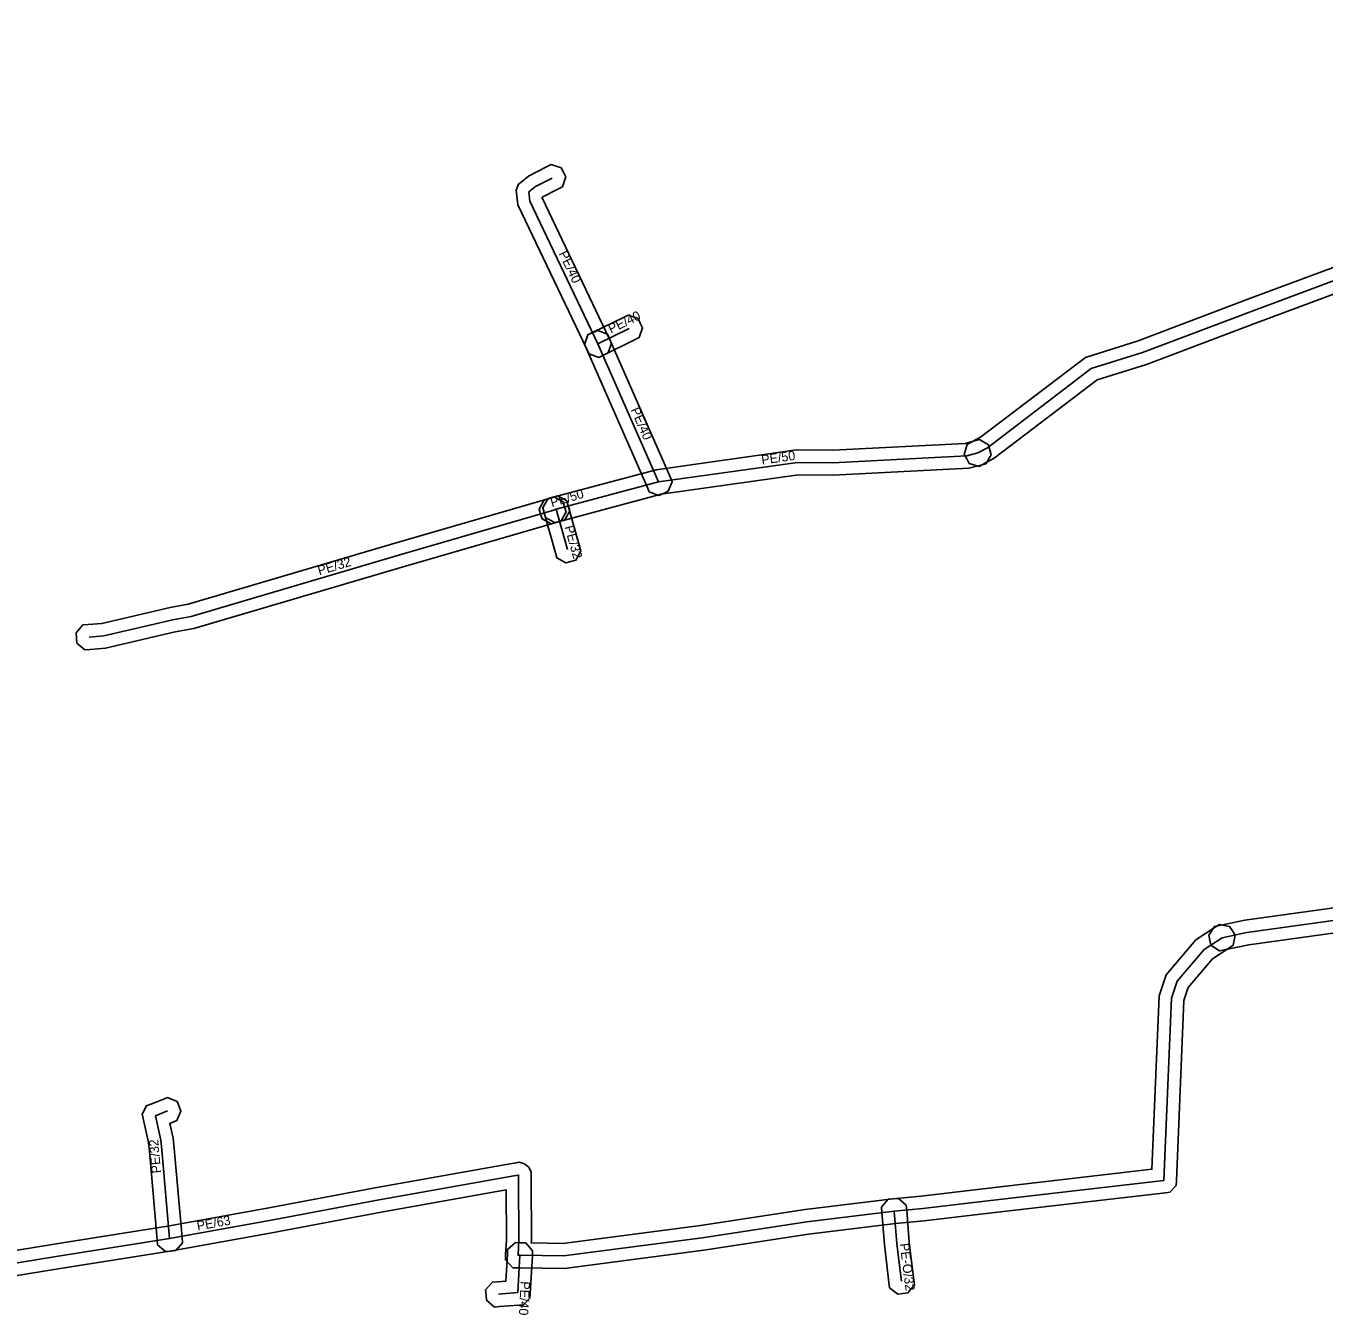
# Model space of a CAD drawing. Extents: x -682697 to -681888, y -1059966 to -1059631.
# Drawn here: x -682102.6 to -681998.6, y -1059783.8 to -1059680.6 of the extents above; entities that cross this region are included whole.
import ezdxf

# ---------------------------------------------------------------- set-up
doc = ezdxf.new("R2010")
doc.units = 0
for name, color, linetype in [('1', 7, 'Continuous'), ('24', 7, 'Continuous'), ('30', 7, 'Continuous')]:
    doc.layers.add(name, color=color, linetype=linetype)

msp = doc.modelspace()

# ---------------------------------------------------------------- linework, layer by layer
at = {"layer": '1'}
for points in [[(-682057.52, -1059706.82), (-682057.7, -1059706.45), (-682063.23, -1059694.88), (-682063.32, -1059693.96), (-682063.35, -1059693.7), (-682063.16, -1059693.23), (-682062.96, -1059693.07), (-682062.36, -1059692.59), (-682060.92, -1059691.85), (-682060.55, -1059691.66), (-682059.76, -1059691.92), (-682059.57, -1059692.28), (-682059.38, -1059692.65), (-682059.64, -1059693.44), (-682060.01, -1059693.63), (-682061.26, -1059694.27), (-682061.28, -1059694.29), (-682061.27, -1059694.32), (-682055.9, -1059705.59), (-682055.72, -1059705.96), (-682055.99, -1059706.74), (-682056.37, -1059706.92), (-682056.74, -1059707.1)], [(-682057.61, -1059705.3), (-682057.24, -1059705.12), (-682054.75, -1059703.9), (-682054.38, -1059703.72), (-682053.59, -1059703.99), (-682053.41, -1059704.36), (-682053.23, -1059704.73), (-682053.5, -1059705.52), (-682053.87, -1059705.7), (-682056.36, -1059706.92), (-682056.73, -1059707.1), (-682057.52, -1059706.83), (-682057.7, -1059706.46), (-682057.88, -1059706.09)], [(-682052.7, -1059717.86), (-682052.87, -1059717.48), (-682057.72, -1059706.42), (-682057.88, -1059706.04), (-682057.58, -1059705.27), (-682057.2, -1059705.1), (-682056.82, -1059704.94), (-682056.05, -1059705.24), (-682055.88, -1059705.62), (-682051.03, -1059716.68), (-682050.87, -1059717.06), (-682051.17, -1059717.83), (-682051.55, -1059718), (-682051.93, -1059718.16)], [(-682025.73, -1059715.63), (-682026.13, -1059715.73), (-682027.09, -1059715.97), (-682037.96, -1059716.54), (-682040.75, -1059716.52), (-682051.75, -1059718.06), (-682059.88, -1059720.24), (-682060.28, -1059720.34), (-682061, -1059719.93), (-682061.11, -1059719.53), (-682061.21, -1059719.13), (-682060.8, -1059718.41), (-682060.4, -1059718.3), (-682052.15, -1059716.1), (-682040.89, -1059714.52), (-682038, -1059714.54), (-682027.39, -1059713.99), (-682026.63, -1059713.79), (-682026.23, -1059713.69), (-682025.51, -1059714.11), (-682025.41, -1059714.51), (-682025.31, -1059714.91)], [(-682059.76, -1059720.2), (-682060.16, -1059720.32), (-682072.4, -1059723.88), (-682089.17, -1059728.82), (-682090.66, -1059729.09), (-682096.24, -1059730.4), (-682097.49, -1059730.5), (-682097.91, -1059730.53), (-682098.54, -1059729.99), (-682098.57, -1059729.58), (-682098.6, -1059729.16), (-682098.06, -1059728.53), (-682097.65, -1059728.5), (-682096.54, -1059728.42), (-682091.06, -1059727.13), (-682089.63, -1059726.88), (-682072.96, -1059721.96), (-682060.72, -1059718.4), (-682060.32, -1059718.28), (-682059.59, -1059718.68), (-682059.48, -1059719.08), (-682059.36, -1059719.48)], [(-682059.46, -1059720.11), (-682059.85, -1059720.23), (-682060.15, -1059720.32), (-682060.55, -1059720.44), (-682061.28, -1059720.04), (-682061.4, -1059719.64), (-682061.52, -1059719.25), (-682061.12, -1059718.52), (-682060.72, -1059718.4), (-682060.43, -1059718.31), (-682060.03, -1059718.19), (-682059.3, -1059718.59), (-682059.18, -1059718.99), (-682059.06, -1059719.38)], [(-682059.29, -1059718.6), (-682059.18, -1059719), (-682058.28, -1059722.22), (-682058.17, -1059722.62), (-682058.57, -1059723.34), (-682058.97, -1059723.45), (-682059.37, -1059723.56), (-682060.09, -1059723.16), (-682060.2, -1059722.76), (-682061.1, -1059719.54), (-682061.21, -1059719.14), (-682060.81, -1059718.42), (-682060.41, -1059718.31), (-682060.01, -1059718.2)], [(-682092.08, -1059778.18), (-682092.12, -1059777.77), (-682092.73, -1059770.67), (-682092.82, -1059769.98), (-682093.24, -1059768.06), (-682093.32, -1059767.71), (-682092.97, -1059767.06), (-682092.63, -1059766.92), (-682091.66, -1059766.53), (-682091.28, -1059766.38), (-682090.52, -1059766.7), (-682090.36, -1059767.09), (-682090.21, -1059767.47), (-682090.53, -1059768.23), (-682090.92, -1059768.39), (-682091.1, -1059768.46), (-682090.84, -1059769.64), (-682090.74, -1059770.47), (-682090.12, -1059777.59), (-682090.09, -1059778.01), (-682090.62, -1059778.64), (-682091.03, -1059778.68), (-682091.45, -1059778.71)], [(-682032.11, -1059775), (-682032.07, -1059775.41), (-682031.86, -1059777.97), (-682031.7, -1059779.3), (-682031.5, -1059780.97), (-682031.45, -1059781.38), (-682031.97, -1059782.03), (-682032.38, -1059782.08), (-682032.79, -1059782.13), (-682033.44, -1059781.61), (-682033.49, -1059781.2), (-682033.68, -1059779.54), (-682033.85, -1059778.17), (-682034.07, -1059775.57), (-682034.1, -1059775.16), (-682033.56, -1059774.53), (-682033.15, -1059774.49), (-682032.74, -1059774.46)], [(-682062.04, -1059778.65), (-682062.06, -1059779.07), (-682062.23, -1059782.07), (-682062.25, -1059782.44), (-682062.78, -1059782.98), (-682063.15, -1059783.01), (-682064.69, -1059783.13), (-682065.1, -1059783.16), (-682065.73, -1059782.62), (-682065.77, -1059782.21), (-682065.8, -1059781.79), (-682065.26, -1059781.17), (-682064.85, -1059781.13), (-682064.18, -1059781.08), (-682064.06, -1059778.95), (-682064.04, -1059778.54), (-682063.42, -1059777.99), (-682063, -1059778.01), (-682062.59, -1059778.03)]]:
    msp.add_lwpolyline(points, close=True, dxfattribs=at)
for points in [[(-681993.93, -1059700.56), (-682004.05, -1059704.33), (-682012.86, -1059707.66), (-682016.81, -1059708.9), (-682025.07, -1059715.18), (-682025.9, -1059715.64), (-682026.27, -1059715.84), (-682027.06, -1059715.6), (-682027.26, -1059715.24), (-682027.46, -1059714.88), (-682027.22, -1059714.08), (-682026.86, -1059713.88), (-682026.16, -1059713.5), (-682017.75, -1059707.1), (-682013.52, -1059705.77), (-682004.75, -1059702.45), (-681994.59, -1059698.68)], [(-681994.67, -1059752.76), (-682004.65, -1059754.16), (-682006.61, -1059754.56), (-682007.01, -1059754.64), (-682007.71, -1059754.19), (-682007.79, -1059753.78), (-682007.87, -1059753.38), (-682007.42, -1059752.68), (-682007.01, -1059752.6), (-682004.99, -1059752.18), (-681994.94, -1059750.78)], [(-682112.46, -1059780.1), (-682100.36, -1059778.13), (-682091.29, -1059776.69), (-682083.3, -1059775.25), (-682074.52, -1059773.59), (-682063.71, -1059771.67), (-682063.33, -1059771.6), (-682063.11, -1059771.57), (-682062.69, -1059771.68), (-682062.52, -1059771.82), (-682062.35, -1059771.97), (-682062.16, -1059772.37), (-682062.16, -1059772.59), (-682062.16, -1059772.97), (-682062.14, -1059777.82), (-682062.15, -1059778.02), (-682059.61, -1059778.07), (-682048.59, -1059776.63), (-682040.21, -1059775.35), (-682033.18, -1059774.5), (-682030.9, -1059774.27), (-682025.94, -1059773.69), (-682012.43, -1059772.12), (-682011.84, -1059758.25), (-682011.29, -1059756.56), (-682008.92, -1059753.76), (-682007.36, -1059752.74), (-682007.01, -1059752.52), (-682006.2, -1059752.69), (-682005.97, -1059753.03), (-682005.75, -1059753.38), (-682005.92, -1059754.19), (-682006.26, -1059754.42), (-682007.58, -1059755.28), (-682009.51, -1059757.56), (-682009.86, -1059758.61), (-682010.47, -1059773.06), (-682010.49, -1059773.43), (-682010.99, -1059773.97), (-682011.35, -1059774.01), (-682025.7, -1059775.67), (-682030.68, -1059776.25), (-682032.96, -1059776.48), (-682039.93, -1059777.33), (-682048.31, -1059778.61), (-682059.49, -1059780.07), (-682063.01, -1059780.01), (-682063.07, -1059780.01), (-682063.2, -1059780.01), (-682063.63, -1059780.01), (-682063.92, -1059779.7), (-682064.22, -1059779.39), (-682064.2, -1059778.96), (-682064.14, -1059777.78), (-682064.16, -1059773.78), (-682074.16, -1059775.55), (-682082.94, -1059777.21), (-682090.95, -1059778.67), (-682100.04, -1059780.11), (-682112.16, -1059782.08)]]:
    msp.add_lwpolyline(points, dxfattribs=at)
at = {"layer": '24'}
for points in [[(-681960.34, -1059680.56), (-681967.57, -1059687.51), (-681969.12, -1059688.59), (-681974.59, -1059692.49), (-681977.51, -1059693.73), (-681993.2, -1059699.26), (-681994.26, -1059699.62), (-682004.4, -1059703.39), (-682013.19, -1059706.71), (-682017.28, -1059708), (-682025.61, -1059714.34), (-682026.38, -1059714.76)], [(-682056.8, -1059706.02), (-682062.25, -1059694.6), (-682062.33, -1059693.85), (-682061.81, -1059693.43), (-682060.46, -1059692.74)], [(-682056.8, -1059706.02), (-682054.31, -1059704.8)], [(-682051.95, -1059717.08), (-682056.8, -1059706.02)], [(-682026.38, -1059714.76), (-682027.24, -1059714.98), (-682037.98, -1059715.54), (-682040.82, -1059715.52), (-682051.95, -1059717.08), (-682060.14, -1059719.27)], [(-682060.44, -1059719.36), (-682072.68, -1059722.92), (-682089.4, -1059727.85), (-682090.86, -1059728.11), (-682096.39, -1059729.41), (-682097.57, -1059729.5)], [(-682060.14, -1059719.27), (-682060.44, -1059719.36)], [(-682060.14, -1059719.27), (-682059.24, -1059722.49)], [(-682006.81, -1059753.58), (-682004.82, -1059753.17), (-681994.8, -1059751.77), (-681979.19, -1059749.59), (-681972.14, -1059748.75), (-681967.35, -1059749.04), (-681961.52, -1059750.33), (-681955.86, -1059751.76), (-681953.56, -1059752.44), (-681952.34, -1059752.85), (-681951.12, -1059753.66)], [(-682006.81, -1059753.58), (-682008.25, -1059754.52), (-682010.4, -1059757.06), (-682010.85, -1059758.43), (-682011.47, -1059773.02), (-682025.82, -1059774.68), (-682030.79, -1059775.26), (-682033.07, -1059775.49), (-682040.07, -1059776.34), (-682048.45, -1059777.62), (-682059.55, -1059779.07), (-682063, -1059779.01), (-682063.06, -1059779.01), (-682063.2, -1059779.01), (-682063.14, -1059777.8), (-682063.16, -1059772.97), (-682063.16, -1059772.59), (-682063.54, -1059772.66), (-682074.34, -1059774.57), (-682083.12, -1059776.23), (-682091.12, -1059777.68), (-682100.2, -1059779.12), (-682112.31, -1059781.09)], [(-682091.12, -1059777.68), (-682091.74, -1059770.57), (-682091.83, -1059769.81), (-682092.26, -1059767.85), (-682091.29, -1059767.46)], [(-682033.07, -1059775.49), (-682032.86, -1059778.07), (-682032.69, -1059779.42), (-682032.49, -1059781.09)], [(-682063.06, -1059779.01), (-682063.23, -1059782.01), (-682064.77, -1059782.13)]]:
    msp.add_lwpolyline(points, dxfattribs=at)

# ---------------------------------------------------------------- texts
at = {"layer": '30'}
for s, rotation, p in [('PE/40', 295.512, (-682059.96, -1059698.78)), ('PE/40', 26.103, (-682055.76, -1059705.21)), ('PE/40', 293.6783, (-682054.2, -1059711.3)), ('PE/50', 7.9787, (-682043.66, -1059715.69)), ('PE/50', 16.5761, (-682060.49, -1059719.11)), ('PE/32', 285.6158, (-682059.49, -1059720.68)), ('PE/32', 16.4285, (-682079.13, -1059724.56)), ('PE/32', 94.9837, (-682091.8, -1059772.42)), ('PE/63', 10.2733, (-682088.87, -1059777.04)), ('PE-O/32', 277.1772, (-682032.63, -1059778.09)), ('PE/40', 266.7567, (-682062.99, -1059781.08))]:
    msp.add_text(s, height=0.75, rotation=rotation, dxfattribs=at).set_placement(p)

doc.saveas('drawing.dxf')
